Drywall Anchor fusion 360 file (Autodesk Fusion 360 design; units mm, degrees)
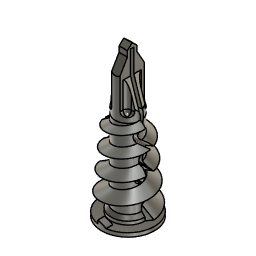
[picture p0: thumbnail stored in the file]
sketch "Sketch1" plane through (0, 0, 0) normal (0, 0, 1) x axis (1, 0, 0)
  circle C1 centre (0, 0) radius 7.925
  point P1 (0, 0)
  point P2 (0, 0)
  coincident P1 P2
  dimension "d1" diameter C1 = 15.85
extrude "Extrude1" new body sketch "Sketch1" along normal blind 1.15
sketch "Sketch2" plane through (0, 0, 1.15) normal (0, 0, 1) x axis (-1, 0, 0)
  circle C1 centre (0, 0) radius 7.925
  circle C2 centre (0, 0) radius 4.1
  point P2 (0, 0)
  point P4 (0, 0)
  coincident P2 P4
  dimension "d4" diameter C2 = 8.2
work_plane "WorkPlane1" sketch "Loft1" AlongDistance 25.5
sketch "Sketch3" plane through (0, 0, 26.65) normal (0, 0, 1) x axis (1, 0, 0)
  circle C1 centre (0, 0) radius 3.85
  point P1 (0, 0)
  point P2 (0, 0)
  coincident P1 P2
  dimension "d6" diameter C1 = 7.7
loft "Loft1"
sketch "Sketch4" plane through (0, 0, 1.15) normal (0, 0, 1) x axis (-1, 0, 0)
  line L1 (-1.25, -7.8258) -> (-1.25, 7.8258)
  line L2 (1.2219, 7.8302) -> (1.25, -7.8258)
  circle C1 centre (0, 0) radius 4.1
  circle C2 centre (0, 0) radius 7.925
  circle C3 centre (0, 0) radius 5.925
  point P1 (0, 0)
  point P3 (0, 0)
  point P4 (-1.25, 7.8258)
  point P5 (1.2219, 7.8302)
  point P6 (-1.25, -7.8258)
  point P7 (1.25, -7.8258)
  coincident P1 P3
  coincident C2 P4
  coincident C2 P5
  coincident C2 P6
  vertical L1
  coincident C2 P7
extrude "Extrude4" add sketch "Sketch4" profile of C2 C3 L1 L2 along normal blind 1
fillet "Fillet1" radius 3.65
fillet "Fillet2" radius 4
work_plane "WorkPlane2" AlongDistance 10.5
work_plane "WorkPlane3" AlongDistance 7
sketch "Sketch5" plane through (0, 0, 37.15) normal (0, 0, 1) x axis (1, 0, 0)
work_plane "WorkPlane4" AlongDistance 0
extrude "Extrude5" add of existing geometry blind 10.5
sketch "Sketch7" plane through (0, 0, 37.15) normal (0, 0, 1) x axis (1, 0, 0)
  line L1 (1.25, 0) -> (-1.25, 0)
  line L2 (1.25, -1.5) -> (1.25, 1.5)
  line L3 (3.5458, -1.5) -> (-3.5458, -1.5)
  line L4 (1.25, -3.6414) -> (1.25, 3.6414)
  line L5 (-1.25, 3.6414) -> (-1.25, -3.6414)
  line L6 (-3.5458, 1.5) -> (3.5458, 1.5)
  circle C1 centre (0, 0) radius 3.85
  point P1 (0, 0)
  point P4 (1.25, 0)
  point P7 (-3.5458, -1.5)
  point P8 (3.5458, -1.5)
  point P9 (1.25, -3.6414)
  point P10 (1.25, 3.6414)
  point P11 (-1.25, -3.6414)
  point P12 (-1.25, 3.6414)
  point P13 (3.5458, 1.5)
  point P14 (-3.5458, 1.5)
  point P3 (-1.25, 0)
  point P5 (1.25, 1.5)
  point P6 (1.25, -1.5)
  horizontal L1
  midpoint P1 L1
  vertical L2
  midpoint P4 L2
  coincident C1 P7
  coincident C1 P8
  perpendicular L2 L3
  coincident C1 P9
  coincident C1 P10
  parallel L2 L4
  coincident C1 P11
  coincident C1 P12
  perpendicular L3 L5
  coincident C1 P13
  coincident C1 P14
  perpendicular L4 L6
  dimension "d26" distance P3 P4 = 2.5
  dimension "d27" distance P5 P6 = 3
extrude "Extrude6" cut sketch "Sketch7" profile of C1 L3 L4 L5 L6 against normal blind 9
fillet "Fillet3" radius 1.25
sketch "Sketch8" plane through (0, 0, 0) normal (1, 0, 0) x axis (0, 1, 0)
  line L1 (0.5, 37.15) -> (-0.5, 37.15)
  point P4 (0, 37.15)
  point P2 (-0.5, 37.15)
  point P3 (0.5, 37.15)
  horizontal L1
  midpoint L1 P4
  dimension "d32" distance P2 P3 = 1
extrude "Extrude7" cut distance 5 Side1WallThickness 8
sketch "Sketch9" plane through (0, 0, 37.15) normal (0, 0, 1) x axis (-1, 0, 0)
  line L1 (3.8174, 0.5) -> (-3.8174, 0.5)
  line L2 (2.5, 1.5) -> (3.5458, 1.5)
  line L3 (1.25, 3.6414) -> (1.25, 2.75)
  line L4 (-1.25, 2.75) -> (-1.25, 3.6414)
  line L5 (-3.5458, 1.5) -> (-2.5, 1.5)
  line L6 (-3.8174, -0.5) -> (3.8174, -0.5)
  line L7 (-2.5, -1.5) -> (-3.5458, -1.5)
  line L8 (-1.25, -3.6414) -> (-1.25, -2.75)
  line L9 (1.25, -2.75) -> (1.25, -3.6414)
  line L10 (3.5458, -1.5) -> (2.5, -1.5)
  line L11 (1.25, -2.75) -> (1.25, 2.75)
  line L12 (-1.25, 2.75) -> (-1.25, -2.75)
  arc A1 centre (0, 0) radius 3.85 clockwise from (3.5458, 1.5) to (3.8174, 0.5)
  arc A2 centre (2.5, 2.75) radius 1.25 clockwise from (2.5, 1.5) to (1.25, 2.75)
  arc A3 centre (0, 0) radius 3.85 clockwise from (-1.25, 3.6414) to (1.25, 3.6414)
  arc A4 centre (-2.5, 2.75) radius 1.25 clockwise from (-1.25, 2.75) to (-2.5, 1.5)
  arc A5 centre (0, 0) radius 3.85 clockwise from (-3.8174, 0.5) to (-3.5458, 1.5)
  arc A6 centre (0, 0) radius 3.85 clockwise from (-3.5458, -1.5) to (-3.8174, -0.5)
  arc A7 centre (-2.5, -2.75) radius 1.25 clockwise from (-2.5, -1.5) to (-1.25, -2.75)
  arc A8 centre (0, 0) radius 3.85 clockwise from (1.25, -3.6414) to (-1.25, -3.6414)
  arc A9 centre (2.5, -2.75) radius 1.25 clockwise from (1.25, -2.75) to (2.5, -1.5)
  arc A10 centre (0, 0) radius 3.85 clockwise from (3.8174, -0.5) to (3.5458, -1.5)
  point P7 (1.25, 2.75)
  point P28 (1.25, 2.75)
  point P24 (1.25, -2.75)
  point P29 (1.25, -2.75)
  point P20 (-1.25, -2.75)
  point P30 (-1.25, -2.75)
  point P11 (-1.25, 2.75)
  point P31 (-1.25, 2.75)
  coincident P7 P28
  coincident P24 P29
  coincident P20 P30
  coincident P11 P31
extrude "Extrude8" add sketch "Sketch9" profile of L1 L3 A3 L4 L6 L8 A8 L9 L11 L12 along normal blind 7
canvas "Canvas1"
sketch "Sketch12" plane through (0, 0, 0) normal (1, 0, 0) x axis (0, 1, 0)
  line L1 (4, 38) -> (0, 45)
  line L2 (0, 45) -> (4, 38)
  line L3 (-4, 38) -> (0, 45)
  line L4 (-7.4804, 46.6567) -> (-4, 38)
  line L5 (8.284, 45.4709) -> (-7.4804, 46.6567)
  line L6 (4, 38) -> (8.284, 45.4709)
extrude "Extrude9" cut sketch "Sketch12" distance 6
sketch "Sketch13" plane through (-1.25, 0, 0) normal (-1, 0, 0) x axis (0, -1, 0)
  line L1 (-3.6414, 38.6275) -> (-0.5, 44.125)
  line L2 (-3.6414, 29.4) -> (-3.6414, 38.6275)
  line L3 (-2.75, 29.4) -> (-3.6414, 29.4)
  line L4 (-2.75, 37.15) -> (-2.75, 29.4)
  line L5 (-0.5, 37.15) -> (-2.75, 37.15)
  line L6 (-0.5, 44.125) -> (-0.5, 37.15)
  line L7 (0.5, 44.125) -> (3.6414, 38.6275)
  line L8 (0.5, 37.15) -> (0.5, 44.125)
  line L9 (2.75, 37.15) -> (0.5, 37.15)
  line L10 (2.75, 29.4) -> (2.75, 37.15)
  line L11 (3.6414, 29.4) -> (2.75, 29.4)
  line L12 (3.6414, 38.6275) -> (3.6414, 29.4)
  line L13 (0.5, 44.125) -> (-0.5, 44.125)
  line L14 (-1.4352, 42.4885) -> (1.4352, 42.4885)
  line L15 (-1.4352, 44.7885) -> (-1.4352, 42.4885)
  line L16 (0.7352, 45.4885) -> (-0.7352, 45.4885)
  line L17 (1.4352, 44.7885) -> (1.4352, 42.4885)
  arc A1 centre (-0.7352, 44.7885) radius 0.7 clockwise from (-1.4352, 44.7885) to (-0.7352, 45.4885)
  arc A2 centre (0.7352, 44.7885) radius 0.7 clockwise from (0.7352, 45.4885) to (1.4352, 44.7885)
  point P2 (-0.5, 44.125)
  point P14 (-0.5, 44.125)
  point P9 (0.5, 44.125)
  point P15 (0.5, 44.125)
  point P16 (1.4352, 42.4885)
  point P17 (-1.4352, 42.4885)
  point P18 (-1.4352, 45.4885)
  coincident P2 P14
  coincident P9 P15
  coincident L7 P16
  coincident L1 P17
  perpendicular L8 L14
  perpendicular L14 L15
  perpendicular L15 L16
  perpendicular L16 L17
  coincident P18 L15
  coincident P18 L16
  tangent L15 A1
  tangent L16 A1
  tangent L17 A2
  tangent L16 A2
  equal A1 A2
  dimension "d40" distance P17 P18 = 3
  dimension "d41" radius A1 = 0.7
extrude "Extrude10" add sketch "Sketch13" profile of L1 L7 L13 L15 L16 L17 A1 A2 against normal blind 2.5
sketch "Sketch14" plane through (-1.25, 0, 0) normal (-1, 0, 0) x axis (0, -1, 0)
  line L1 (-3.6414, 38.6275) -> (-1.4352, 42.4885)
  line L2 (-3.6414, 29.4) -> (-3.6414, 38.6275)
  line L3 (-2.75, 29.4) -> (-3.6414, 29.4)
  line L4 (-2.75, 37.15) -> (-2.75, 29.4)
  line L5 (-0.5, 37.15) -> (-2.75, 37.15)
  line L6 (-0.5, 44.125) -> (-0.5, 37.15)
  line L7 (0.5, 44.125) -> (-0.5, 44.125)
  line L8 (0.5, 37.15) -> (0.5, 44.125)
  line L9 (2.75, 37.15) -> (0.5, 37.15)
  line L10 (2.75, 29.4) -> (2.75, 37.15)
  line L11 (3.6414, 29.4) -> (2.75, 29.4)
  line L12 (3.6414, 38.6275) -> (3.6414, 29.4)
  line L13 (1.4352, 42.4885) -> (3.6414, 38.6275)
  line L14 (1.4352, 44.7885) -> (1.4352, 42.4885)
  line L15 (-0.7352, 45.4885) -> (0.7352, 45.4885)
  line L16 (-1.4352, 42.4885) -> (-1.4352, 44.7885)
  line L17 (0, 45.4885) -> (-1.4352, 44.1544)
  line L18 (1.4352, 44.1544) -> (0, 45.4885)
  arc A1 centre (0.7352, 44.7885) radius 0.7 clockwise from (0.7352, 45.4885) to (1.4352, 44.7885)
  arc A2 centre (-0.7352, 44.7885) radius 0.7 clockwise from (-1.4352, 44.7885) to (-0.7352, 45.4885)
  point P22 (-1.4352, 44.1544)
  point P23 (0, 45.4885)
  point P24 (1.4352, 44.1544)
  coincident L16 P22
  midpoint L15 P23
  coincident L14 P24
extrude "Extrude11" cut sketch "Sketch14" profile of L14 A1 L15 A2 L16 L17 L18 against normal blind 4.3
sketch "Sketch15" plane through (0, -1.5, 0) normal (0, -1, 0) x axis (1, 0, 0)
  line L1 (-2.5, 29.4) -> (-3.5458, 29.4)
  line L2 (-2.5, 37.15) -> (-2.5, 29.4)
  line L3 (-3.5458, 37.15) -> (-2.5, 37.15)
  line L4 (-3.5458, 29.4) -> (-3.5458, 37.15)
  line L5 (2.5, 29.4) -> (2.5, 37.15)
  line L6 (3.5458, 29.4) -> (2.5, 29.4)
  line L7 (3.5458, 37.15) -> (3.5458, 29.4)
  line L8 (2.5, 37.15) -> (3.5458, 37.15)
  line L9 (3.85, 26.65) -> (-3.85, 26.65)
  line L10 (1.25, 29.4) -> (1.25, 38.6275)
  curve K1 (1.25, 29.4) -> (2.5, 28.15)
  line L11 (2.6944, 28.15) -> (2.5, 28.15)
  curve K2 (2.6944, 28.15) -> (3.5458, 29.4)
  line L12 (3.5458, 37.15) -> (3.5458, 29.4)
  line L13 (3.5458, 37.15) -> (3.8174, 37.15)
  line L14 (3.8174, 29.15) -> (3.8174, 37.15)
  line L15 (3.85, 29.15) -> (3.8174, 29.15)
  line L16 (3.8174, 37.15) -> (3.8174, 29.15)
  line L17 (3.5458, 37.15) -> (3.8174, 37.15)
  line L18 (3.5458, 29.4) -> (3.5458, 37.15)
  curve K3 (3.5458, 29.4) -> (2.6944, 28.15)
  line L19 (2.6944, 28.15) -> (2.5, 28.15)
  curve K4 (2.5, 28.15) -> (1.25, 29.4)
  line L20 (1.25, 38.6275) -> (1.25, 29.4)
  line L21 (-1.25, 29.4) -> (-1.25, 38.6275)
  curve K5 (-1.25, 29.4) -> (-2.5, 28.15)
  line L22 (-2.5, 28.15) -> (-2.6944, 28.15)
  curve K6 (-2.6944, 28.15) -> (-3.5458, 29.4)
  line L23 (-3.5458, 37.15) -> (-3.5458, 29.4)
  line L24 (-3.8174, 37.15) -> (-3.5458, 37.15)
  line L25 (-3.8174, 29.15) -> (-3.8174, 37.15)
  line L26 (-3.8174, 29.15) -> (-3.85, 29.15)
  line L27 (-3.8174, 37.15) -> (-3.8174, 29.15)
  line L28 (-3.8174, 37.15) -> (-3.5458, 37.15)
  line L29 (-3.5458, 29.4) -> (-3.5458, 37.15)
  curve K7 (-3.5458, 29.4) -> (-2.6944, 28.15)
  line L30 (-2.5, 28.15) -> (-2.6944, 28.15)
  curve K8 (-2.5, 28.15) -> (-1.25, 29.4)
  line L31 (-1.25, 38.6275) -> (-1.25, 29.4)
  line L32 (-2.5, 37.15) -> (-1.25, 37.15)
  line L33 (1.25, 37.15) -> (2.5, 37.15)
  line L34 (-3.85, 29.15) -> (-1.25, 37.15)
  line L35 (3.85, 29.15) -> (1.25, 37.15)
  closed curve K9 centre (0, 45)
  closed curve K10 centre (0, 45)
  point P31 (-1.25, 37.15)
  point P35 (-1.25, 37.15)
  point P30 (-3.85, 29.15)
  point P36 (-3.85, 29.15)
  point P34 (1.25, 37.15)
  point P37 (1.25, 37.15)
  point P22 (3.85, 29.15)
  point P38 (3.85, 29.15)
  coincident P31 P35
  coincident P30 P36
  coincident P34 P37
  coincident P22 P38
extrude "Extrude12" cut sketch "Sketch15" profile of L2 L3 L4 L5 L7 L8 L12 L13 L14 L16 L17 L18 L23 L24 L25 L27 L28 L29 L32 L33 L34 L35 distance -6.5
work_plane "WorkPlane5" AlongDistance 1.6
sketch "Sketch16" plane through (0, 0, 0) normal (0, 0, -1) x axis (1, 0, 0)
  circle C1 centre (0, 0) radius 7.925
coil_primitive "CoilPrimitive1" Diameter 15.6 SectionSize 4 TaperAngle -5 Height 23
sketch "Sketch22" plane through (0, 0, 0) normal (1, 0, 0) x axis (0, 1, 0)
  line L1 (-0.2188, 11) -> (0.2188, 11)
  line L2 (0.5, 37.15) -> (0.5, 29.2503)
  line L3 (-0.5, 29.2503) -> (-0.5, 37.15)
  line L4 (0.5, 14.9951) -> (1.1889, 12.2428)
  line L5 (-0.5, 14.9951) -> (-1.1889, 12.2428)
  curve K1 (0, 25.4501) -> (0, 14.9951)
  curve K2 (0.5636, 18.2042) -> (-0.3614, 16.4903)
  curve K3 (1.0458, 26.6143) -> (-1.0458, 24.2859)
  curve K4 (1.0124, 20.6647) -> (1.5266, 18.8261)
  curve K5 (-1.6158, 23.4893) -> (-1, 21.5)
  line L6 (0, 14.9951) -> (0.8035, 13.7824)
  line L7 (-0.8035, 13.7824) -> (0, 14.9951)
  arc A1 centre (-4.5485, 27.3063) radius 4.9127 clockwise from (0, 29.1625) to (0, 25.4501)
  arc A2 centre (0.2188, 12) radius 1 clockwise from (1.1889, 12.2428) to (0.2188, 11)
  arc A3 centre (-0.2188, 12) radius 1 clockwise from (-0.2188, 11) to (-1.1889, 12.2428)
  point P11 (0.1011, 17.3472)
  point P14 (0, 25.4501)
  point P12 (1.2695, 19.7454)
  point P13 (-1.3079, 22.4946)
  point P2 (1.5, 11)
  point P3 (-1.5, 11)
  point P31 (0.8035, 13.7824)
  point P32 (-0.8035, 13.7824)
  horizontal L1
  midpoint P11 K2
  midpoint P14 K3
  midpoint P12 K4
  midpoint P13 K5
  coincident P2 L1
  coincident P2 L4
  tangent L1 A2
  tangent L4 A2
  coincident P3 L1
  coincident P3 L5
  tangent L1 A3
  tangent L5 A3
  equal A2 A3
  coincident L4 P31
  coincident L5 P32
  dimension "d56" distance P2 P3 = 3
  dimension "d58" radius A2 = 1
extrude "Extrude13" cut sketch "Sketch22" profile of L1 L4 L5 A2 A3 L6 L7 distance 10.5 Side1WallThickness 1
sketch "Sketch24" plane through (0, 0, 0) normal (1, 0, 0) x axis (0, 1, 0)
  line L1 (-0.4625, 28.9725) -> (-0.5, 29.15)
  line L2 (0.1425, 28.8941) -> (-0.4625, 28.9725)
  line L3 (0.016, 29.4927) -> (0.1425, 28.8941)
  line L4 (-0.5, 29.15) -> (0.016, 29.4927)
  line L5 (1.2, 11.6) -> (0.3, 14.7)
  line L6 (-0.4, 11) -> (1.2, 11.6)
  line L7 (-1.4, 12.1) -> (-0.4, 11)
  line L8 (0.3, 14.7) -> (-1.4, 12.1)
  parallel L1 L3
extrude "Extrude14" cut sketch "Sketch24" profile of L1 L2 L3 L4 distance 7.5
extrude "Extrude15" cut sketch "Sketch24" profile of L5 L6 L7 L8 distance 8.6
sketch "Sketch25" plane through (0, 0, 0) normal (0, 0, -1) x axis (1, 0, 0)
  line L1 (3.25, 0) -> (-3.25, 0)
  line L2 (0, 3.25) -> (0, -3.25)
  circle C1 centre (0, 0) radius 7.925
  point P1 (0, 0)
  point P3 (-3.25, 0)
  point P4 (3.25, 0)
  point P5 (0, -3.25)
  point P6 (0, 3.25)
  horizontal L1
  midpoint P1 L1
  vertical L2
  midpoint P1 L2
  dimension "d66" distance P3 P4 = 6.5
  dimension "d67" distance P5 P6 = 6.5
extrude "Extrude16" cut blind -5 Side1WallThickness 2
combine "Combine1"
combine "Combine2"
fillet "Fillet6" radius 0.75
chamfer "Chamfer3" distance 2.5
sketch "Sketch26" plane through (0, 0, 1.15) normal (0, 0, 1) x axis (-1, 0, 0)
  line L1 (-4.1, 0) -> (-5.0287, 0)
  curve K1 (-5.0287, 0) -> (-3.4787, -2.17)
  line L2 (1.25, -7.8258) -> (1.2463, -5.7924)
  line L3 (1.2255, 5.7969) -> (1.2219, 7.8302)
  line L4 (-1.25, 7.8258) -> (-1.25, 5.7916)
  line L5 (-1.25, -5.7916) -> (-1.25, -7.8258)
  arc A1 centre (0, 0) radius 4.1 clockwise from (-4.1, 0) to (-3.4787, -2.17)
  arc A2 centre (0, 0) radius 7.925 clockwise from (1.2219, 7.8302) to (1.25, -7.8258)
  arc A3 centre (0, 0) radius 5.925 clockwise from (-1.25, 5.7916) to (1.2255, 5.7969)
  arc A4 centre (0, 0) radius 7.925 clockwise from (-1.25, -7.8258) to (-1.25, 7.8258)
  arc A5 centre (0, 0) radius 5.925 clockwise from (1.2463, -5.7924) to (-1.25, -5.7916)
  circle C1 centre (0, 0) radius 5.1
  concentric A1 C1
extrude "Extrude17" add sketch "Sketch26" profile of L1 A1 K1 C1 along normal blind 2
chamfer "Chamfer4" distance 1
sketch "Sketch27" plane through (0, 0, 5) normal (0, 0, -1) x axis (1, 0, 0)
  line L1 (0.75, 0.75) -> (0.75, -0.75)
  line L2 (-0.75, 0.75) -> (0.75, 0.75)
  line L3 (-0.75, -0.75) -> (-0.75, 0.75)
  line L4 (0.75, -0.75) -> (-0.75, -0.75)
  circle C1 centre (0, 0) radius 1.6
  point P1 (0, 0)
  point P6 (0, 0)
  coincident P1 P6
  dimension "d81" diameter C1 = 3.2
extrude "Extrude18" cut sketch "Sketch27" distance -21.5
